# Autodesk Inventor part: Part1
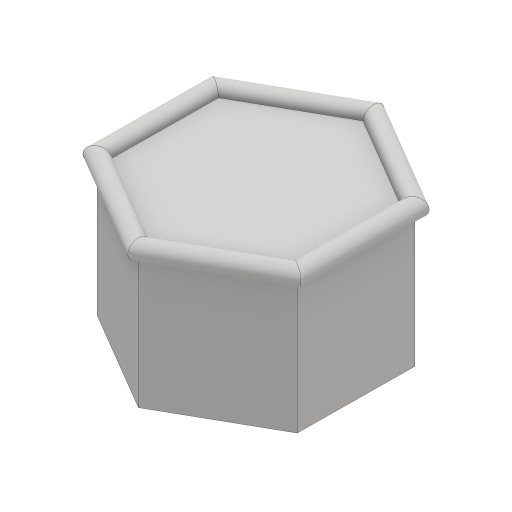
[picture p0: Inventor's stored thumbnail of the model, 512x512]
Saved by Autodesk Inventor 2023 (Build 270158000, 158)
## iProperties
Created: 2015-07
Part Number: Part1
Material: Generic
Document SubType Name: Modeling
Designer: Sandeep
Density: 1 g/cm^3
Appearance: Default
Author: Sandeep
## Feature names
1. Extrusion1
2. Sweep2
## Parameters: d0 = 8 mm, d1 = 0, d4 = 0, d5 = 0
